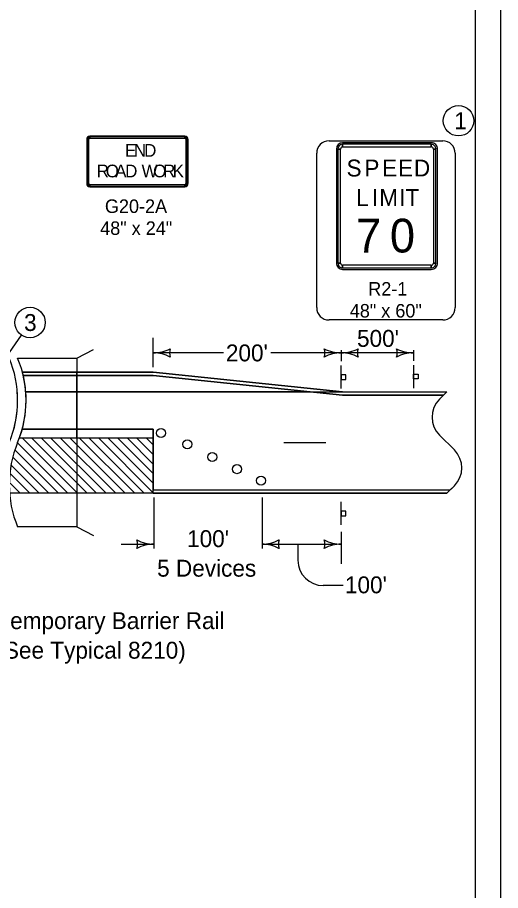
# Model space of a CAD drawing. Extents: x 10133 to 81668, y 4177 to 11018.
# Drawn here: x 30695 to 31268, y 8767 to 9800 of the extents above; entities that cross this region are included whole.
import ezdxf

# ---------------------------------------------------------------- set-up
doc = ezdxf.new("R2010")
doc.units = 0
for name, color, linetype in [('dsnNonPlotable', 7, 'Continuous'), ('dsnShtPlotShapeBatchPrint', 7, 'Continuous'), ('dsnStdBlockModified', 7, 'Continuous'), ('dsnStdDimension', 7, 'Continuous'), ('dsnStdLabel', 7, 'Continuous'), ('dsnStdNote', 7, 'Continuous'), ('dsnStdShading', 7, 'Continuous'), ('Level 2', 7, 'Continuous'), ('SheetBorder', 7, 'Continuous')]:
    doc.layers.add(name, color=color, linetype=linetype)

msp = doc.modelspace()

# ---------------------------------------------------------------- linework, layer by layer
at = {"layer": 'dsnNonPlotable'}
for p, q in [((30777.1, 9656.1), (30777.1, 9603.6)), ((30778, 9656.1), (30779.6, 9656.1)), ((30893.3, 9659.9), (30780.8, 9659.9)), ((30780.8, 9657.4), (30780.8, 9658.9)), ((30893.3, 9658.9), (30893.3, 9657.4)), ((30894.6, 9656.1), (30896.1, 9656.1)), ((30897.1, 9603.6), (30897.1, 9656.1)), ((31072.9, 9644.6), (31072.9, 9509.6)), ((31074.8, 9644.6), (31077.9, 9644.6)), ((31185.4, 9652.1), (31080.4, 9652.1)), ((31080.4, 9647.1), (31080.4, 9650.2)), ((31185.4, 9650.2), (31185.4, 9647.1)), ((31187.9, 9644.6), (31191, 9644.6)), ((31192.9, 9509.6), (31192.9, 9644.6)), ((30779.6, 9603.6), (30778, 9603.6)), ((30896.1, 9603.6), (30894.6, 9603.6)), ((30780.8, 9600.8), (30780.8, 9602.4)), ((30780.8, 9599.9), (30893.3, 9599.9)), ((30893.3, 9602.4), (30893.3, 9600.8)), ((31077.9, 9509.6), (31074.8, 9509.6)), ((31080.4, 9504), (31080.4, 9507.1)), ((31080.4, 9502.1), (31185.4, 9502.1)), ((31185.4, 9507.1), (31185.4, 9504)), ((31191, 9509.6), (31187.9, 9509.6)), ((31078.6, 9361), (31078.6, 9388.5)), ((31164.2, 9388.9), (31164.2, 9361.4)), ((30856, 9376.6), (31080.2, 9353.1)), ((31080.2, 9353.1), (31200, 9353.1)), ((30713.7, 9312.8), (30700.6, 9312.8)), ((30765.2, 9312.8), (30713.7, 9312.8)), ((30856, 9312.8), (30765.2, 9312.8)), ((30765.2, 9312.8), (30765.2, 9302.8)), ((30765.2, 9302.8), (30765.2, 9312.8)), ((30856, 9302.8), (30856, 9312.8)), ((30695.1, 9296.8), (30754.8, 9237.1)), ((30697.4, 9302.8), (30710.5, 9302.8)), ((30700.4, 9302.8), (30766.1, 9237.1)), ((30710.5, 9302.8), (30765.2, 9302.8)), ((30711.7, 9302.8), (30777.4, 9237.1)), ((30723, 9302.8), (30788.7, 9237.1)), ((30734.3, 9302.8), (30800, 9237.1)), ((30745.6, 9302.8), (30811.4, 9237.1)), ((30756.9, 9302.8), (30822.7, 9237.1)), ((30765.2, 9302.8), (30856, 9302.8)), ((30768.3, 9302.8), (30834, 9237.1)), ((30779.6, 9302.8), (30845.3, 9237.1)), ((30790.9, 9302.8), (30856, 9237.7)), ((30802.2, 9302.8), (30856, 9249)), ((30813.5, 9302.8), (30856, 9260.3)), ((30824.8, 9302.8), (30856, 9271.6)), ((30836.1, 9302.8), (30856, 9283)), ((30847.4, 9302.8), (30856, 9294.3)), ((30856, 9237.1), (30856, 9302.8)), ((30692, 9288.5), (30743.5, 9237.1)), ((30689.4, 9279.8), (30732.2, 9237.1)), ((30687.3, 9270.6), (30720.8, 9237.1)), ((30685.9, 9260.7), (30709.5, 9237.1)), ((30685.2, 9250), (30698.2, 9237.1)), ((30766.1, 9237.1), (30765.2, 9238)), ((30765.2, 9238), (30765.2, 9237.1)), ((30765.2, 9237.1), (30766.1, 9237.1)), ((31078.6, 9199.5), (31078.6, 9227))]:
    msp.add_line(p, q, dxfattribs=at)
for points in [[(30778, 9656.1), (30778, 9603.6), (30779.6, 9603.6), (30779.6, 9656.1), (30778, 9656.1)], [(30893.3, 9658.9), (30780.8, 9658.9), (30780.8, 9657.4), (30893.3, 9657.4), (30893.3, 9658.9)], [(30896.1, 9603.6), (30896.1, 9656.1), (30894.6, 9656.1), (30894.6, 9603.6), (30896.1, 9603.6)], [(31074.8, 9644.6), (31074.8, 9509.6), (31077.9, 9509.6), (31077.9, 9644.6), (31074.8, 9644.6)], [(31185.4, 9650.2), (31080.4, 9650.2), (31080.4, 9647.1), (31185.4, 9647.1), (31185.4, 9650.2)], [(31191, 9509.6), (31191, 9644.6), (31187.9, 9644.6), (31187.9, 9509.6), (31191, 9509.6)], [(30780.8, 9600.8), (30893.3, 9600.8), (30893.3, 9602.4), (30780.8, 9602.4), (30780.8, 9600.8)], [(31080.4, 9504), (31185.4, 9504), (31185.4, 9507.1), (31080.4, 9507.1), (31080.4, 9504)], [(31078.7, 9377.4), (31078.7, 9371.8), (31084.3, 9371.8), (31084.3, 9377.4)], [(31164.3, 9372.5), (31164.3, 9378.1), (31170, 9378.1), (31170, 9372.5)], [(31078.7, 9216), (31078.7, 9210.3), (31084.3, 9210.3), (31084.3, 9216)]]:
    msp.add_lwpolyline(points, close=True, dxfattribs=at)
for points in [[(31064.3, 9654.3), (31199.1, 9654.3)], [(31049.6, 9456.9), (31049.6, 9639.6)], [(31213.8, 9639.6), (31213.8, 9456.9)], [(31199.1, 9442.2), (31064.3, 9442.2)]]:
    msp.add_lwpolyline(points, dxfattribs=at)
for centre in [(30865.2, 9308.3), (30865.2, 9308.3), (30896.2, 9295), (30896.2, 9295), (30925.8, 9279.9), (30925.8, 9279.9), (30955.1, 9265.6), (30955.1, 9265.6), (30983.7, 9252), (30983.7, 9252)]:
    msp.add_circle(centre, 5.37, dxfattribs=at)
for centre, radius, start, end in [((30780.8, 9656.1), 3.75, 90.0002, 179.9998), ((30780.8, 9656.1), 2.81, 90.0002, 179.9998), ((30780.8, 9656.1), 1.25, 90.0002, 179.9998), ((30893.3, 9656.1), 3.75, 0, 90.0002), ((30893.3, 9656.1), 2.81, 0, 90.0002), ((30893.3, 9656.1), 1.25, 0, 90.0002), ((31064.3, 9639.6), 14.7, 90, 180), ((31080.4, 9644.6), 7.5, 90.0002, 179.9998), ((31080.4, 9644.6), 5.62, 90.0002, 179.9998), ((31080.4, 9644.6), 2.5, 90.0002, 179.9998), ((31185.4, 9644.6), 7.5, 0, 90.0002), ((31185.4, 9644.6), 5.62, 0, 90.0002), ((31185.4, 9644.6), 2.5, 0, 90.0002), ((31199.1, 9639.6), 14.7, 0, 90), ((30780.8, 9603.6), 3.75, 179.9998, 270.0001), ((30780.8, 9603.6), 2.81, 179.9998, 270.0001), ((30780.8, 9603.6), 1.25, 179.9998, 270.0001), ((30893.3, 9603.6), 3.75, 270.0001, 0.0003), ((30893.3, 9603.6), 2.81, 270.0001, 0.0003), ((30893.3, 9603.6), 1.25, 270.0001, 0.0003), ((31080.4, 9509.6), 7.5, 179.9998, 270.0001), ((31080.4, 9509.6), 5.62, 179.9998, 270.0001), ((31080.4, 9509.6), 2.5, 179.9998, 270.0001), ((31185.4, 9509.6), 7.5, 270.0001, 0.0003), ((31185.4, 9509.6), 5.62, 270.0001, 0.0003), ((31185.4, 9509.6), 2.5, 270.0001, 0.0003), ((31064.3, 9456.9), 14.7, 180, 270), ((31199.1, 9456.9), 14.7, 270, 0), ((30856, 9445.7), 42.5, 270, 298.0725), ((30891.6, 9403.2), 16.4, 162.2666, 197.7334), ((31042.9, 9403.2), 16.4, 342.2667, 17.7334), ((31078.6, 9445.7), 42.5, 241.9275, 270), ((31078.6, 9445.7), 42.5, 270, 298.0725), ((31114.2, 9403.2), 16.4, 162.2666, 197.7334), ((31128.6, 9403.2), 16.4, 342.2667, 17.7334), ((31164.2, 9445.7), 42.5, 241.9275, 270), ((30856, 9360.7), 42.5, 61.9275, 90), ((31078.6, 9360.7), 42.5, 90, 118.0725), ((31078.6, 9360.7), 42.5, 61.9275, 90), ((31164.2, 9360.7), 42.5, 90, 118.0725), ((30575.2, 9347.1), 130, 340.0918, 344.7168)]:
    msp.add_arc(centre, radius, start, end, dxfattribs=at)
at = {"layer": 'dsnShtPlotShapeBatchPrint'}
msp.add_line((31237.5, 9884), (31237.5, 8414), dxfattribs=at)
at = {"layer": 'dsnStdBlockModified'}
msp.add_lwpolyline([(28132.5, 9934), (31267.5, 9934), (31267.5, 7924), (28132.5, 7924)], close=True, dxfattribs=at)
at = {"layer": 'dsnStdDimension'}
for p, q in [((30765.2, 9380.6), (30700.8, 9380.6)), ((30700.8, 9380.6), (30856, 9380.6)), ((30700.8, 9380.6), (30713.9, 9380.6)), ((30701.8, 9376.6), (30714.9, 9376.6)), ((30714.9, 9376.6), (30765.2, 9376.6)), ((30856, 9380.6), (30765.2, 9380.6)), ((30765.2, 9380.6), (30765.2, 9376.6)), ((30765.2, 9376.6), (30765.2, 9380.6)), ((30765.2, 9376.6), (30856, 9376.6)), ((30856, 9376.6), (30765.2, 9376.6)), ((30765.2, 9376.6), (30765.2, 9357.1)), ((30765.2, 9357.1), (30765.2, 9376.6)), ((30856, 9380.6), (31080.2, 9357.1)), ((31080.2, 9357.1), (30856, 9380.6)), ((30856, 9376.6), (31042, 9357.1)), ((31042, 9357.1), (30856, 9376.6)), ((30765.2, 9357.1), (30704.8, 9357.1)), ((30704.8, 9357.1), (30765.2, 9357.1)), ((30765.2, 9357.1), (30998.4, 9357.1)), ((30765.2, 9312.8), (30765.2, 9357.1)), ((30765.2, 9357.1), (30765.2, 9312.8)), ((30998.4, 9357.1), (31204, 9357.1)), ((30998.4, 9357.1), (31042, 9357.1)), ((31042, 9357.1), (31080.2, 9357.1)), ((31080.2, 9353.1), (31042, 9357.1)), ((31042, 9357.1), (31080.2, 9357.1)), ((31080.2, 9353.1), (31042, 9357.1)), ((31080.2, 9357.1), (31204, 9357.1)), ((31204, 9357.1), (31200, 9353.1)), ((31200, 9353.1), (31080.2, 9353.1)), ((31200, 9353.1), (31080.2, 9353.1)), ((31195.2, 9348.3), (31200, 9353.1)), ((30700.6, 9312.8), (30713.7, 9312.8)), ((30713.7, 9312.8), (30765.2, 9312.8)), ((30765.2, 9312.8), (30856, 9312.8)), ((30856, 9312.8), (30856, 9302.8)), ((31212.8, 9288.3), (31195.2, 9305.8)), ((30856, 9302.8), (30856, 9297.1)), ((30856, 9297.1), (30856, 9294.3)), ((30856, 9294.3), (30856, 9283)), ((30856, 9283), (30856, 9271.6)), ((30856, 9249), (30856, 9241.1)), ((31208, 9241.1), (31212.8, 9245.8)), ((30856, 9237.1), (30685.6, 9237.1)), ((30856, 9241.1), (31208, 9241.1)), ((30856, 9241.1), (31208, 9241.1)), ((31204, 9237.1), (30856, 9237.1)), ((30856, 9237.1), (31204, 9237.1)), ((31208, 9241.1), (31204, 9237.1))]:
    msp.add_line(p, q, dxfattribs=at)
for points in [[(30765.2, 9376.6), (30714.9, 9376.6), (30701.8, 9376.6)], [(31042, 9357.1), (30998.4, 9357.1), (30765.2, 9357.1)], [(30998.4, 9357.1), (30998.4, 9357.1)], [(31080.2, 9357.1), (31080.2, 9357.1)], [(31200, 9353.1), (31200, 9353.1)], [(31200, 9353.1), (31200, 9353.1)], [(30856, 9271.6), (30856, 9260.3), (30856, 9249)], [(30856, 9237.1), (30856, 9237.7), (30856, 9241.1)], [(31208, 9241.1), (31208, 9241.1)], [(31208, 9241.1), (31208, 9241.1)]]:
    msp.add_lwpolyline(points, dxfattribs=at)
for centre, radius, start, end in [((30575.2, 9347.1), 130, 13.1174, 14.9346), ((30575.2, 9347.1), 130, 4.4108, 13.1174), ((30565.2, 9347.1), 130, 344.7177, 4.4117), ((30575.2, 9347.1), 130, 344.7168, 4.4108), ((31216.4, 9327.1), 30, 135, 225), ((31191.6, 9267.1), 30, 315, 45)]:
    msp.add_arc(centre, radius, start, end, dxfattribs=at)
at = {"layer": 'dsnStdLabel'}
for p, q in [((30765.2, 9397.1), (30785.2, 9407.1)), ((30695.2, 9397.1), (30765.2, 9397.1)), ((30701.8, 9376.6), (30856, 9376.6)), ((30856, 9376.6), (31080.2, 9353.1)), ((30704.8, 9357.1), (31080.2, 9357.1)), ((31204, 9357.1), (31195.2, 9348.3)), ((30856, 9312.8), (30700.6, 9312.8)), ((30856, 9302.8), (30856, 9312.8)), ((31195.2, 9305.8), (31212.8, 9288.3)), ((30697.4, 9302.8), (30856, 9302.8)), ((31212.8, 9245.8), (31204, 9237.1)), ((30765.2, 9197.1), (30785.2, 9187.1))]:
    msp.add_line(p, q, dxfattribs=at)
for points in [[(30765.2, 9397.1), (30765.2, 9197.1), (30695.2, 9197.1)], [(31080.2, 9353.1), (31200, 9353.1)], [(30713.7, 9312.8), (30700.6, 9312.8)], [(30697.4, 9302.8), (30710.5, 9302.8)], [(31010.6, 9297.1), (31060.6, 9297.1)], [(30856, 9241.1), (31208, 9241.1)]]:
    msp.add_lwpolyline(points, dxfattribs=at)
for centre, radius, start, end in [((30565.2, 9347.1), 130, 337.3801, 22.6199), ((30575.2, 9347.1), 130, 337.3801, 22.6199), ((31216.4, 9327.1), 30, 135, 225), ((30815.2, 9247.1), 130, 157.3801, 202.6199), ((31191.6, 9267.1), 30, 315, 45)]:
    msp.add_arc(centre, radius, start, end, dxfattribs=at)
at = {"layer": 'dsnStdNote'}
for p, q in [((30606.6, 9290.1), (30699.6, 9424.4)), ((30856, 9386.2), (30856, 9421.2)), ((30939.1, 9403.2), (30856, 9403.2)), ((31078.6, 9403.2), (30995.4, 9403.2)), ((30856.5, 9232), (30856.5, 9171.8)), ((30985, 9232), (30985, 9171.8)), ((31078.6, 9191.5), (31078.6, 9153.5)), ((30817.7, 9176.8), (30856.6, 9176.8)), ((30985, 9176.8), (31069.7, 9176.8)), ((31027.4, 9176.8), (31027.4, 9157.7)), ((31081, 9127.7), (31057.4, 9127.7))]:
    msp.add_line(p, q, dxfattribs=at)
for centre, radius, start, end in [((30820.9, 9176.8), 16.4, 342.2667, 17.7334), ((30856.6, 9219.3), 42.5, 241.9275, 270), ((30984.9, 9219.3), 42.5, 270, 298.0725), ((31020.6, 9176.8), 16.4, 162.2666, 197.7334), ((31043, 9176.8), 16.4, 342.2667, 17.7334), ((31078.6, 9219.3), 42.5, 241.9275, 270), ((30856.6, 9134.3), 42.5, 90, 118.0725), ((30984.9, 9134.3), 42.5, 61.9275, 90), ((31078.6, 9134.3), 42.5, 90, 118.0725), ((31057.4, 9157.7), 30, 180, 270)]:
    msp.add_arc(centre, radius, start, end, dxfattribs=at)
at = {"layer": 'dsnStdShading'}
for p, q in [((31078.6, 9406.5), (31078.6, 9393.6)), ((31164.2, 9403.2), (31078.6, 9403.2)), ((31164.2, 9406.5), (31164.2, 9393.8))]:
    msp.add_line(p, q, dxfattribs=at)
at = {"layer": 'Level 2'}
for centre in [(31217.7, 9678.1), (30709.9, 9439.2)]:
    msp.add_circle(centre, 18, dxfattribs=at)
at = {"layer": 'SheetBorder'}
msp.add_lwpolyline([(28132.5, 9944), (31267.5, 9944), (31267.5, 7924), (28132.5, 7924)], close=True, dxfattribs=at)

# ---------------------------------------------------------------- texts
at = {"layer": 'dsnNonPlotable'}
for s, height, p in [('E', 15, (30822.4, 9635.5)), ('N', 15, (30833, 9635.5)), ('D', 15, (30845.1, 9635.5)), ('R', 15, (30788.9, 9611.1)), ('O', 15, (30799.6, 9611.1)), ('A', 15, (30810.8, 9611.1)), ('D', 15, (30822.6, 9611.1)), ('W', 15, (30842.1, 9611.1)), ('O', 15, (30855.8, 9611.1)), ('R', 15, (30867.6, 9611.1)), ('K', 15, (30878.9, 9611.1)), ('S', 20, (31085, 9612.1)), ('P', 20, (31106.1, 9612.1)), ('E', 20, (31127.2, 9612.1)), ('E', 20, (31146, 9612.1)), ('D', 20, (31164.8, 9612.1)), ('L', 20, (31096.3, 9577.1)), ('I', 20, (31115.1, 9577.1)), ('M', 20, (31123.7, 9577.1)), ('I', 20, (31147.3, 9577.1)), ('T', 20, (31154.8, 9577.1)), ('G20-2A', 16, (30798.6, 9568.9)), ('7', 40, (31096.3, 9522.1)), ('0', 40, (31136.4, 9522.1)), ('48" x 24"', 16, (30793, 9542.9)), ('R2-1', 16, (31110.7, 9471.1)), ('48" x 60"', 16, (31088.8, 9445.1))]:
    msp.add_text(s, height=height, dxfattribs=at).set_placement(p)
at = {"layer": 'dsnStdNote'}
for s, p in [("100'", (30896, 9173.3)), ('5 Devices', (30860.5, 9138.3)), ("100'", (31083.1, 9118.6)), ('Temporary Barrier Rail', (30670, 9076.2)), ('(See Typical 8210)', (30670, 9041.2))]:
    msp.add_text(s, height=20, dxfattribs=at).set_placement(p)
at = {"layer": 'dsnStdShading'}
for s, p in [("500'", (31097.4, 9410.4)), ("200'", (30942, 9393.2))]:
    msp.add_text(s, height=20, dxfattribs=at).set_placement(p)
at = {"layer": 'Level 2'}
for s, p in [('1', (31212.6, 9668.1)), ('3', (30702.8, 9429.2))]:
    msp.add_text(s, height=20, dxfattribs=at).set_placement(p)

doc.saveas('drawing.dxf')
